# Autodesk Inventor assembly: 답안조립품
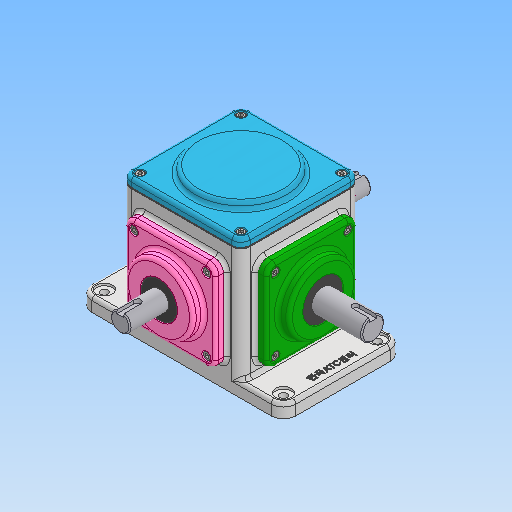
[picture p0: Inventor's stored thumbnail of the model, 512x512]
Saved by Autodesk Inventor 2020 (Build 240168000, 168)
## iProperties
Created: 2021-11
Part Number: 답안조립품
Document SubType Name: Assembly
Designer: user
Author: user
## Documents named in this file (16)
- C:\Users\user\Desktop\611112V1002\답안조립품.iam
- C:\Users\user\Desktop\611112V1002\볼트 M4.ipt
- C:\Users\user\Desktop\611112V1002\상부커버.ipt
- C:\Users\user\Desktop\611112V1002\서브베벨기어.ipt
- C:\Users\user\Desktop\611112V1002\서브축.ipt
- C:\Users\user\Desktop\611112V1002\서브커버.ipt
- C:\Users\user\Desktop\611112V1002\오일 실 17 32 8.ipt
- C:\Users\user\Desktop\611112V1002\오일 실 20 35 8.ipt
- C:\Users\user\Desktop\611112V1002\키 4x4.ipt
- C:\Users\user\Desktop\611112V1002\개스킷.ipt
- C:\Users\user\Desktop\611112V1002\메인베벨기어.ipt
- C:\Users\user\Desktop\611112V1002\메인축.ipt
- C:\Users\user\Desktop\611112V1002\메인커버.ipt
- C:\Users\user\Desktop\611112V1002\베어링 6203.ipt
- C:\Users\user\Desktop\611112V1002\베어링 6204.ipt
- C:\Users\user\Desktop\611112V1002\본체.ipt
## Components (1 placed, 1 different names)
1. 개스킷:1
